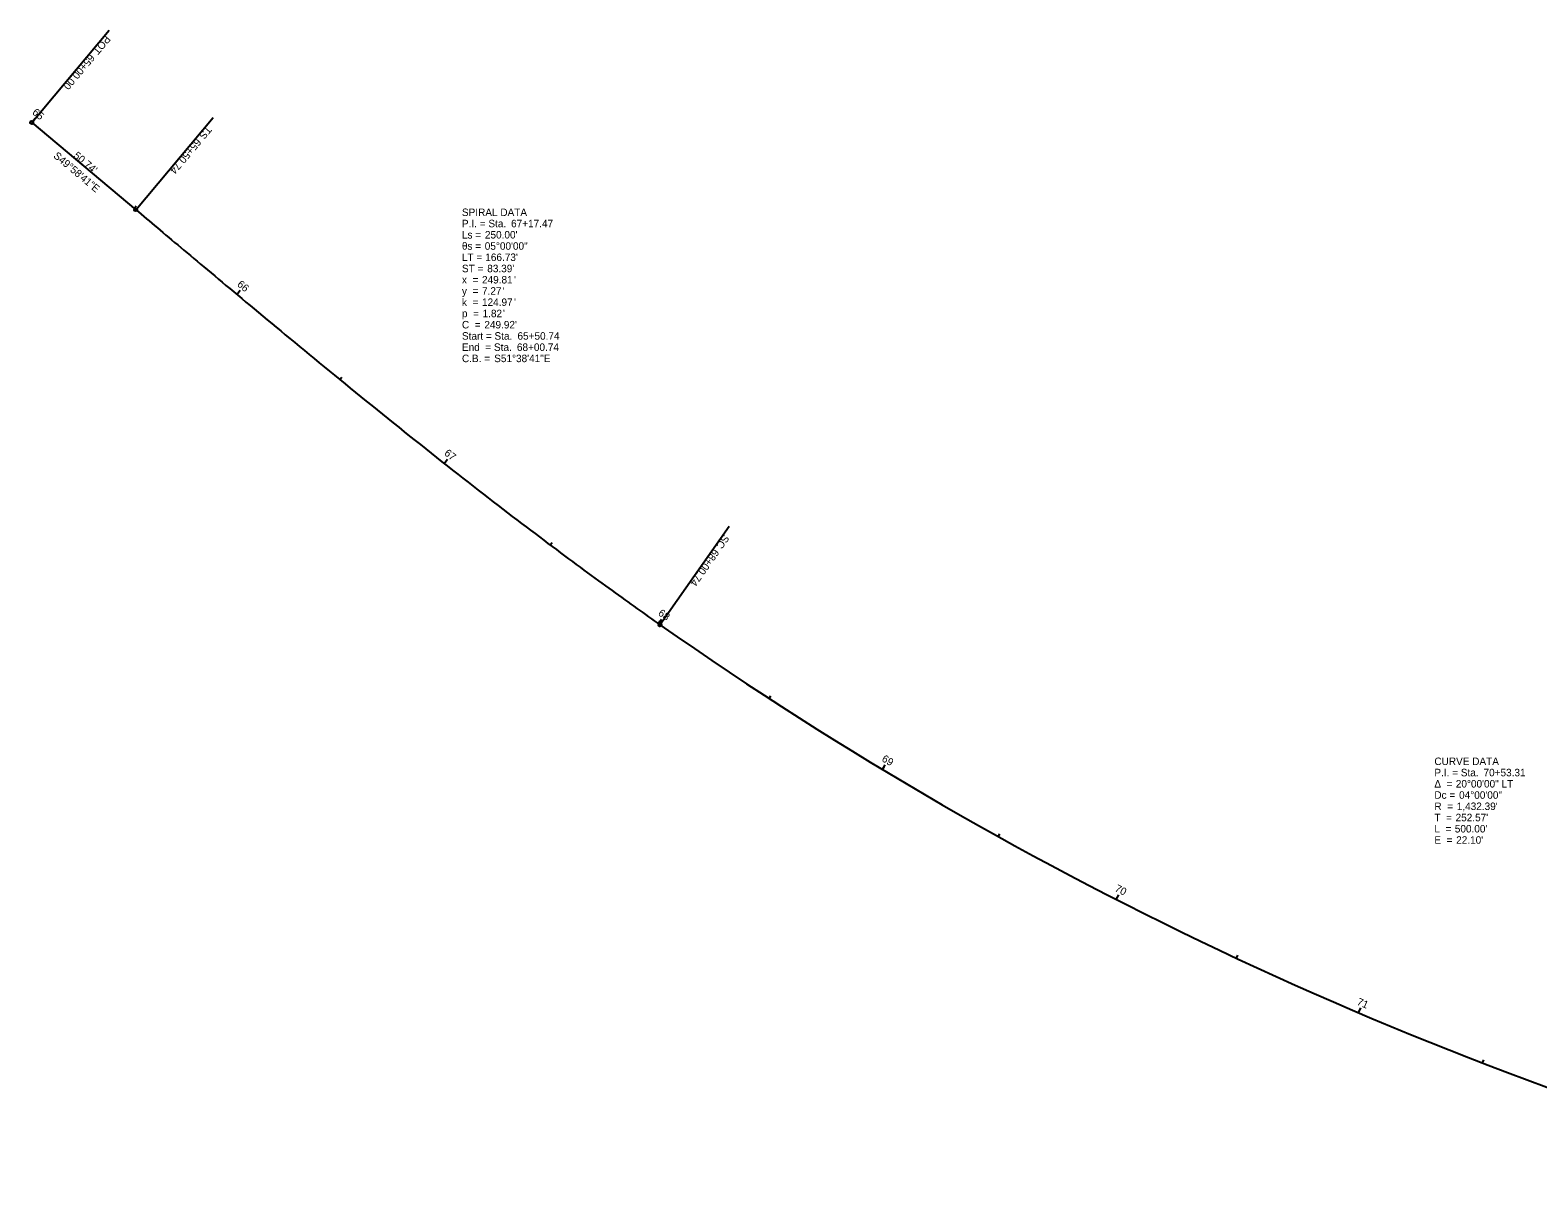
# Model space of a CAD drawing. Extents: x 1999336 to 2003366, y 252766 to 253936.
# Drawn here: x 1999336 to 1999900, y 253504 to 253936 of the extents above; entities that cross this region are included whole.
import ezdxf

# ---------------------------------------------------------------- set-up
doc = ezdxf.new("R2010")
doc.units = 0
for name, color, linetype in [('GE_X_CL_20', 7, 'Continuous'), ('GK_Visualization', 7, 'Continuous'), ('RW_X_Esmt_SH', 7, 'Continuous'), ('SC_Scratch3', 7, 'Continuous'), ('SV_X_Control_Cells_Found', 7, 'Continuous'), ('SV_X_Text_Elevation', 7, 'Continuous'), ('SV_X_Text_Name', 7, 'Continuous')]:
    doc.layers.add(name, color=color, linetype=linetype)

msp = doc.modelspace()

# ---------------------------------------------------------------- linework, layer by layer
at = {"layer": 'GE_X_CL_20'}
for p, q in [((1999336.91, 253901.92), (1999365.85, 253936.38)), ((1999336.91, 253901.92), (1999338.2, 253903.45)), ((1999375.77, 253869.29), (1999404.71, 253903.75)), ((1999413.53, 253837.66), (1999414.3, 253838.58)), ((1999491.06, 253774.5), (1999491.8, 253775.44)), ((1999571.75, 253714.21), (1999597.57, 253751.06)), ((1999571.14, 253714.63), (1999571.83, 253715.62)), ((1999654.94, 253660.11), (1999655.56, 253661.13)), ((1999742.34, 253611.56), (1999743.25, 253613.34)), ((1999832.92, 253569.22), (1999833.39, 253570.33))]:
    msp.add_line(p, q, dxfattribs=at)
for centre in [(1999336.91, 253901.92), (1999375.77, 253869.29), (1999571.75, 253714.21)]:
    msp.add_circle(centre, 0.6, dxfattribs=at)
at = {"layer": 'GK_Visualization'}
msp.add_line((1999336.91, 253901.92), (1999375.77, 253869.29), dxfattribs=at)
msp.add_arc((2000393.78, 254887.24), 1432.39, 234.97811, 254.97808, dxfattribs=at)
msp.add_arc((2000393.78, 254887.24), 1432.39, 234.97811, 254.97808, dxfattribs=at)
msp.add_open_spline([(1999375.77, 253869.29), (1999381.09, 253864.83), (1999391.72, 253855.89), (1999413.02, 253838.06), (1999439.71, 253815.86), (1999472.01, 253789.53), (1999504.68, 253763.67), (1999532.33, 253742.66), (1999554.74, 253726.25), (1999566.06, 253718.2), (1999571.75, 253714.21)], degree=3, dxfattribs=at)
msp.add_open_spline([(1999375.77, 253869.29), (1999381.09, 253864.83), (1999391.72, 253855.89), (1999413.02, 253838.06), (1999439.71, 253815.86), (1999472.01, 253789.53), (1999504.68, 253763.67), (1999532.33, 253742.66), (1999554.74, 253726.25), (1999566.06, 253718.2), (1999571.75, 253714.21)], degree=3, dxfattribs=at)
at = {"layer": 'SC_Scratch3'}
for p, q in [((1999336.91, 253901.92), (1999365.85, 253936.38)), ((1999336.91, 253901.92), (1999338.2, 253903.45)), ((1999375.77, 253869.29), (1999404.71, 253903.75)), ((1999375.2, 253869.77), (1999375.97, 253870.69)), ((1999413.53, 253837.66), (1999414.81, 253839.19)), ((1999452.07, 253805.81), (1999452.83, 253806.74)), ((1999491.06, 253774.5), (1999492.29, 253776.07)), ((1999571.75, 253714.21), (1999597.57, 253751.06)), ((1999530.68, 253744.01), (1999531.4, 253744.97)), ((1999571.14, 253714.63), (1999572.29, 253716.27)), ((1999612.56, 253686.64), (1999613.22, 253687.65)), ((1999654.94, 253660.11), (1999655.97, 253661.82)), ((1999698.22, 253635.07), (1999698.8, 253636.12)), ((1999742.34, 253611.56), (1999743.25, 253613.34)), ((1999787.26, 253589.6), (1999787.77, 253590.69)), ((1999832.92, 253569.22), (1999833.7, 253571.06)), ((1999879.26, 253550.45), (1999879.69, 253551.57))]:
    msp.add_line(p, q, dxfattribs=at)
for centre in [(1999336.91, 253901.92), (1999375.77, 253869.29), (1999571.75, 253714.21)]:
    msp.add_circle(centre, 0.6, dxfattribs=at)
at = {"layer": 'SV_X_Text_Name'}
for p, q in [((1999336.91, 253901.92), (1999365.85, 253936.38)), ((1999336.91, 253901.92), (1999337.68, 253902.84)), ((1999375.77, 253869.29), (1999404.71, 253903.75)), ((1999571.75, 253714.21), (1999597.57, 253751.06)), ((1999742.34, 253611.56), (1999743.25, 253613.34))]:
    msp.add_line(p, q, dxfattribs=at)
for centre in [(1999336.91, 253901.92), (1999375.77, 253869.29), (1999571.75, 253714.21)]:
    msp.add_circle(centre, 0.6, dxfattribs=at)

# ---------------------------------------------------------------- texts
at = {"layer": 'GE_X_CL_20'}
for s, rotation, p in [('POT', 229.9781, (1999364.47, 253934.66)), ('65+00.00', 229.9781, (1999358.59, 253927.67)), ('65', 319.9781, (1999336.86, 253905.29)), ('TS', 229.9781, (1999402.32, 253900.83)), ('65+50.74', 229.9781, (1999398.4, 253896.17)), ('S49°58\'41"E', 319.9781, (1999344.77, 253889.05)), ("50.74'", 319.9781, (1999352.24, 253889.11)), ('SC', 234.9781, (1999595.57, 253748.13)), ('68+00.74', 234.9781, (1999591.83, 253742.78)), ('70', 332.9485, (1999741.55, 253614.82))]:
    msp.add_text(s, height=2.8, rotation=rotation, dxfattribs=at).set_placement(p)
at = {"layer": 'RW_X_Esmt_SH'}
for s, p in [('SPIRAL DATA', (1999497.72, 253866.93)), ('P.I. = Sta. ', (1999497.72, 253862.73)), ('67+17.47', (1999516.09, 253862.73)), ('Ls = ', (1999497.72, 253858.53)), ("250.00'", (1999506.31, 253858.53)), ('θs = ', (1999497.72, 253854.33)), ('LT = ', (1999497.72, 253850.13)), ('05°00\'00"', (1999506.25, 253854.33)), ("166.73'", (1999506.45, 253850.13)), ('ST = ', (1999497.72, 253845.93)), ("83.39'", (1999507.18, 253845.93)), ('x  = ', (1999497.72, 253841.73)), ('249.81', (1999505.22, 253841.73)), ("'", (1999517.18, 253841.73)), ('y  = ', (1999497.72, 253837.53)), ('k  = ', (1999497.72, 253833.33)), ('7.27', (1999505.22, 253837.53)), ('124.97', (1999505.22, 253833.33)), ("'", (1999512.83, 253837.53)), ("'", (1999517.18, 253833.33)), ('p  = ', (1999497.72, 253829.13)), ('1.82', (1999505.44, 253829.13)), ("'", (1999513.05, 253829.13)), ('Start = Sta. ', (1999497.72, 253820.73)), ('C  = ', (1999497.72, 253824.93)), ("249.92'", (1999506.09, 253824.93)), ('65+50.74', (1999518.48, 253820.73)), ('End  = Sta. ', (1999497.72, 253816.53)), ('68+00.74', (1999518.27, 253816.53)), ('C.B. = ', (1999497.72, 253812.33)), ('S51°38\'41"E', (1999509.78, 253812.33)), ('CURVE DATA', (1999861.23, 253661.78)), ('P.I. = Sta. ', (1999861.23, 253657.58)), ('70+53.31', (1999879.6, 253657.58)), ('Δ  = ', (1999861.23, 253653.38)), ('20°00\'00" LT', (1999869.25, 253653.38)), ('Dc = ', (1999861.23, 253649.18)), ('04°00\'00"', (1999870.47, 253649.18)), ('T  = ', (1999861.23, 253640.78)), ('R  = ', (1999861.23, 253644.98)), ("252.57'", (1999869.16, 253640.78)), ("1,432.39'", (1999869.6, 253644.98)), ('L  = ', (1999861.23, 253636.58)), ("500.00'", (1999868.87, 253636.58)), ('E  = ', (1999861.23, 253632.38)), ("22.10'", (1999869.38, 253632.38))]:
    msp.add_text(s, height=2.8, dxfattribs=at).set_placement(p)
at = {"layer": 'SC_Scratch3'}
for s, rotation, p in [('POT', 229.9781, (1999364.47, 253934.66)), ('65+00.00', 229.9781, (1999358.59, 253927.67)), ('65', 319.9781, (1999336.86, 253905.29)), ('TS', 229.9781, (1999402.32, 253900.83)), ('65+50.74', 229.9781, (1999398.4, 253896.17)), ('S49°58\'41"E', 319.9781, (1999344.77, 253889.05)), ("50.74'", 319.9781, (1999352.24, 253889.11)), ('66', 320.1722, (1999413.47, 253841.02)), ('67', 321.7604, (1999490.86, 253777.89)), ('SC', 234.9781, (1999595.57, 253748.13)), ('68+00.74', 234.9781, (1999591.83, 253742.78)), ('68', 324.9486, (1999570.81, 253717.98)), ('69', 328.9485, (1999654.4, 253663.41)), ('70', 332.9485, (1999741.55, 253614.82)), ('71', 336.9485, (1999832.03, 253572.32))]:
    msp.add_text(s, height=2.8, rotation=rotation, dxfattribs=at).set_placement(p)
at = {"layer": 'SV_X_Control_Cells_Found'}
for s, p in [('SPIRAL DATA', (1999497.72, 253866.93)), ('P.I. = Sta. ', (1999497.72, 253862.73)), ('67+17.47', (1999516.09, 253862.73)), ('Ls = ', (1999497.72, 253858.53)), ("250.00'", (1999506.31, 253858.53)), ('θs = ', (1999497.72, 253854.33)), ('LT = ', (1999497.72, 253850.13)), ('05°00\'00"', (1999506.25, 253854.33)), ("166.73'", (1999506.45, 253850.13)), ('ST = ', (1999497.72, 253845.93)), ("83.39'", (1999507.18, 253845.93)), ('x  = ', (1999497.72, 253841.73)), ('249.81', (1999505.22, 253841.73)), ("'", (1999517.18, 253841.73)), ('y  = ', (1999497.72, 253837.53)), ('k  = ', (1999497.72, 253833.33)), ('7.27', (1999505.22, 253837.53)), ('124.97', (1999505.22, 253833.33)), ("'", (1999512.83, 253837.53)), ("'", (1999517.18, 253833.33)), ('p  = ', (1999497.72, 253829.13)), ('1.82', (1999505.44, 253829.13)), ("'", (1999513.05, 253829.13)), ('Start = Sta. ', (1999497.72, 253820.73)), ('C  = ', (1999497.72, 253824.93)), ("249.92'", (1999506.09, 253824.93)), ('65+50.74', (1999518.48, 253820.73)), ('End  = Sta. ', (1999497.72, 253816.53)), ('68+00.74', (1999518.27, 253816.53)), ('C.B. = ', (1999497.72, 253812.33)), ('S51°38\'41"E', (1999509.78, 253812.33)), ('CURVE DATA', (1999861.23, 253661.78)), ('P.I. = Sta. ', (1999861.23, 253657.58)), ('70+53.31', (1999879.6, 253657.58)), ('Δ  = ', (1999861.23, 253653.38)), ('20°00\'00" LT', (1999869.25, 253653.38)), ('Dc = ', (1999861.23, 253649.18)), ('04°00\'00"', (1999870.47, 253649.18)), ('T  = ', (1999861.23, 253640.78)), ('R  = ', (1999861.23, 253644.98)), ("252.57'", (1999869.16, 253640.78)), ("1,432.39'", (1999869.6, 253644.98)), ('L  = ', (1999861.23, 253636.58)), ("500.00'", (1999868.87, 253636.58)), ('E  = ', (1999861.23, 253632.38)), ("22.10'", (1999869.38, 253632.38))]:
    msp.add_text(s, height=2.8, dxfattribs=at).set_placement(p)
at = {"layer": 'SV_X_Text_Elevation'}
for s, p in [('SPIRAL DATA', (1999497.72, 253866.93)), ('P.I. = Sta. ', (1999497.72, 253862.73)), ('67+17.47', (1999516.09, 253862.73)), ('Ls = ', (1999497.72, 253858.53)), ("250.00'", (1999506.31, 253858.53)), ('θs = ', (1999497.72, 253854.33)), ('LT = ', (1999497.72, 253850.13)), ('05°00\'00"', (1999506.25, 253854.33)), ("166.73'", (1999506.45, 253850.13)), ('ST = ', (1999497.72, 253845.93)), ("83.39'", (1999507.18, 253845.93)), ('x  = ', (1999497.72, 253841.73)), ('249.81', (1999505.22, 253841.73)), ("'", (1999517.18, 253841.73)), ('y  = ', (1999497.72, 253837.53)), ('k  = ', (1999497.72, 253833.33)), ('7.27', (1999505.22, 253837.53)), ('124.97', (1999505.22, 253833.33)), ("'", (1999512.83, 253837.53)), ("'", (1999517.18, 253833.33)), ('p  = ', (1999497.72, 253829.13)), ('1.82', (1999505.44, 253829.13)), ("'", (1999513.05, 253829.13)), ('Start = Sta. ', (1999497.72, 253820.73)), ('C  = ', (1999497.72, 253824.93)), ("249.92'", (1999506.09, 253824.93)), ('65+50.74', (1999518.48, 253820.73)), ('End  = Sta. ', (1999497.72, 253816.53)), ('68+00.74', (1999518.27, 253816.53)), ('C.B. = ', (1999497.72, 253812.33)), ('S51°38\'41"E', (1999509.78, 253812.33)), ('CURVE DATA', (1999861.23, 253661.78)), ('P.I. = Sta. ', (1999861.23, 253657.58)), ('70+53.31', (1999879.6, 253657.58)), ('Δ  = ', (1999861.23, 253653.38)), ('20°00\'00" LT', (1999869.25, 253653.38)), ('Dc = ', (1999861.23, 253649.18)), ('04°00\'00"', (1999870.47, 253649.18)), ('T  = ', (1999861.23, 253640.78)), ('R  = ', (1999861.23, 253644.98)), ("252.57'", (1999869.16, 253640.78)), ("1,432.39'", (1999869.6, 253644.98)), ('L  = ', (1999861.23, 253636.58)), ("500.00'", (1999868.87, 253636.58)), ('E  = ', (1999861.23, 253632.38)), ("22.10'", (1999869.38, 253632.38))]:
    msp.add_text(s, height=2.8, dxfattribs=at).set_placement(p)
at = {"layer": 'SV_X_Text_Name'}
for s, rotation, p in [('POT', 229.9781, (1999364.47, 253934.66)), ('65+00.00', 229.9781, (1999358.59, 253927.67)), ('TS', 229.9781, (1999402.32, 253900.83)), ('65+50.74', 229.9781, (1999398.4, 253896.17)), ('S49°58\'41"E', 319.9781, (1999344.77, 253889.05)), ("50.74'", 319.9781, (1999352.24, 253889.11)), ('SC', 234.9781, (1999595.57, 253748.13)), ('68+00.74', 234.9781, (1999591.83, 253742.78)), ('70', 332.9485, (1999741.55, 253614.82))]:
    msp.add_text(s, height=2.8, rotation=rotation, dxfattribs=at).set_placement(p)

doc.saveas('drawing.dxf')
